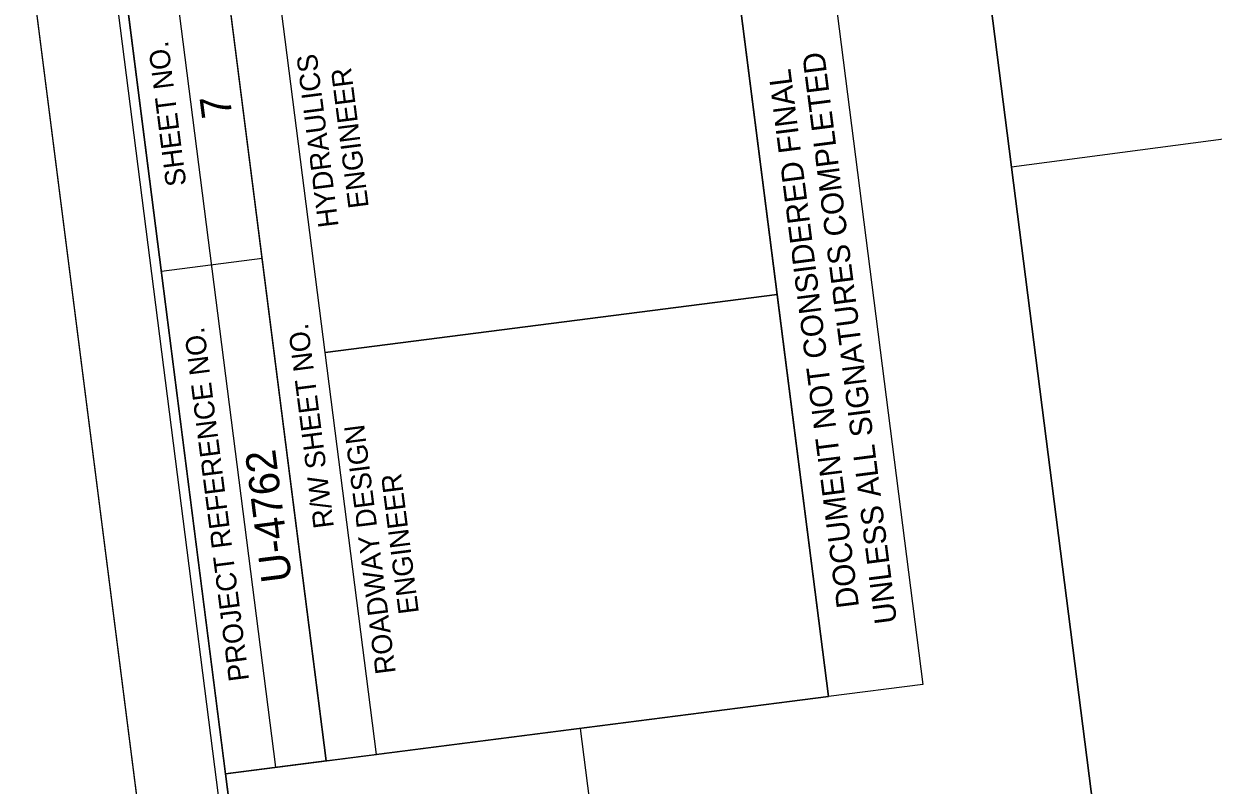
# Model space of a CAD drawing. Extents: x 2368054 to 2369353, y 804567 to 806376.
# Drawn here: x 2368053.8 to 2368347.5, y 806021.8 to 806209.8 of the extents above; entities that cross this region are included whole.
import ezdxf

# ---------------------------------------------------------------- set-up
doc = ezdxf.new("R2010")
doc.units = 0
for name, color, linetype in [('Old_Level_10', 7, 'Continuous'), ('Old_Level_15', 7, 'Continuous'), ('Old_Level_2', 7, 'Continuous'), ('Old_Level_3', 7, 'Continuous'), ('Old_Level_4', 7, 'Continuous'), ('Old_Level_6', 7, 'Continuous'), ('Plan Sheet CELL', 7, 'Continuous'), ('Plot Label CELL', 7, 'Continuous'), ('Plot Shape CELL', 7, 'Continuous')]:
    doc.layers.add(name, color=color, linetype=linetype)

msp = doc.modelspace()

# ---------------------------------------------------------------- linework, layer by layer
at = {"layer": 'Old_Level_10'}
for points in [[(2368268.35, 804735.15), (2369309.86, 804868.2), (2369119.83, 806356.11), (2368288.07, 806249.88), (2368318.38, 806012.56), (2368108.6, 805985.76)], [(2368318.38, 806012.56), (2368288.07, 806249.9), (2368078.28, 806223.14), (2368108.6, 805985.76)]]:
    msp.add_lwpolyline(points, close=True, dxfattribs=at)
at = {"layer": 'Old_Level_15'}
msp.add_line((2368053.83, 806237.11), (2368267.11, 804567.18), dxfattribs=at)
at = {"layer": 'Old_Level_2'}
msp.add_lwpolyline([(2369128.07, 804972.39), (2369136.27, 804907.55), (2368256.12, 804830.92), (2368108.6, 805985.76), (2368318.38, 806012.56), (2368297.7, 806174.49), (2369009.69, 806268.56), (2369034.65, 806345.24), (2369119.83, 806356.12), (2369293.89, 804993.26)], close=True, dxfattribs=at)
msp.add_lwpolyline([(2369128.07, 804972.39), (2369136.27, 804907.55), (2368256.12, 804830.92), (2368108.6, 805985.76), (2368318.38, 806012.56), (2368297.7, 806174.49), (2369009.69, 806268.56), (2369034.65, 806345.24), (2369119.83, 806356.12), (2369293.89, 804993.26)], close=True, dxfattribs=at)
at = {"layer": 'Old_Level_3'}
msp.add_lwpolyline([(2368103.62, 806024.66), (2368117.1, 805919.15), (2368204.74, 805930.34), (2368191.26, 806035.85)], close=True, dxfattribs=at)
at = {"layer": 'Old_Level_4'}
msp.add_lwpolyline([(2369331.8, 804716.26), (2369120.73, 806368.83), (2368074.24, 806235.18), (2368285.3, 804582.61)], close=True, dxfattribs=at)
at = {"layer": 'Old_Level_6'}
msp.add_lwpolyline([(2369353.29, 804705.9), (2369140, 806375.84), (2368053.83, 806237.11), (2368267.11, 804567.18)], close=True, dxfattribs=at)
at = {"layer": 'Plan Sheet CELL'}
for p, q in [((2368250.44, 806245.08), (2368275.78, 806046.66)), ((2368250.44, 806245.08), (2368275.78, 806046.66)), ((2368252.47, 806043.68), (2368227.13, 806242.11)), ((2368252.47, 806043.68), (2368227.13, 806242.11)), ((2368275.78, 806046.66), (2368252.47, 806043.68)), ((2368275.78, 806046.66), (2368252.47, 806043.68))]:
    msp.add_line(p, q, dxfattribs=at)
at = {"layer": 'Plot Shape CELL'}
for p, q in [((2368128.51, 806027.84), (2368103.14, 806226.26)), ((2368128.51, 806027.84), (2368103.14, 806226.26)), ((2368116.07, 806026.24), (2368090.74, 806224.68)), ((2368087.86, 806148.67), (2368112.65, 806151.89)), ((2368128.22, 806128.66), (2368239.77, 806142.92)), ((2368128.51, 806027.84), (2368140.89, 806029.42))]:
    msp.add_line(p, q, dxfattribs=at)
for points in [[(2368078.28, 806223.12), (2368268.32, 804735.17), (2369309.86, 804868.2), (2369119.83, 806356.12)], [(2369309.86, 804868.2), (2368268.35, 804735.15), (2368103.62, 806024.66), (2368252.47, 806043.68), (2368227.14, 806242.11), (2369119.83, 806356.12)], [(2368128.22, 806128.66), (2368115.54, 806227.84), (2368227.14, 806242.11), (2368239.82, 806142.92)], [(2368103.62, 806024.66), (2368078.28, 806223.12), (2368103.14, 806226.26), (2368128.51, 806027.84)], [(2368140.89, 806029.42), (2368128.22, 806128.66), (2368239.82, 806142.92), (2368252.47, 806043.68)]]:
    msp.add_lwpolyline(points, close=True, dxfattribs=at)

# ---------------------------------------------------------------- texts
at = {"layer": 'Plan Sheet CELL'}
for s, p in [('UNLESS ALL SIGNATURES COMPLETED', (2368269.44, 806061.98)), ('UNLESS ALL SIGNATURES COMPLETED', (2368269.44, 806061.98)), ('DOCUMENT NOT CONSIDERED FINAL', (2368260.06, 806065.89)), ('DOCUMENT NOT CONSIDERED FINAL', (2368260.06, 806065.89))]:
    msp.add_text(s, height=5.5, rotation=97.2784, dxfattribs=at).set_placement(p)
at = {"layer": 'Plot Label CELL'}
for s, p in [('7', (2368105.33, 806186.96)), ('U-4762', (2368120.03, 806072.35))]:
    msp.add_text(s, height=7.5, rotation=97.2784, dxfattribs=at).set_placement(p)
at = {"layer": 'Plot Shape CELL'}
for s, height, p in [('SHEET NO.', 5, (2368093.97, 806169.97)), ('HYDRAULICS', 5, (2368131.57, 806159.8)), ('ENGINEER', 5, (2368139, 806164.54)), ('PROJECT REFERENCE NO.', 5.0001, (2368109.46, 806047.78)), ('R/W SHEET NO.', 5.0001, (2368130.4, 806085.54)), ('ROADWAY DESIGN', 5.0001, (2368145.68, 806049.56)), ('ENGINEER', 5, (2368151.38, 806064.39))]:
    msp.add_text(s, height=height, rotation=97.2784, dxfattribs=at).set_placement(p)

doc.saveas('drawing.dxf')
